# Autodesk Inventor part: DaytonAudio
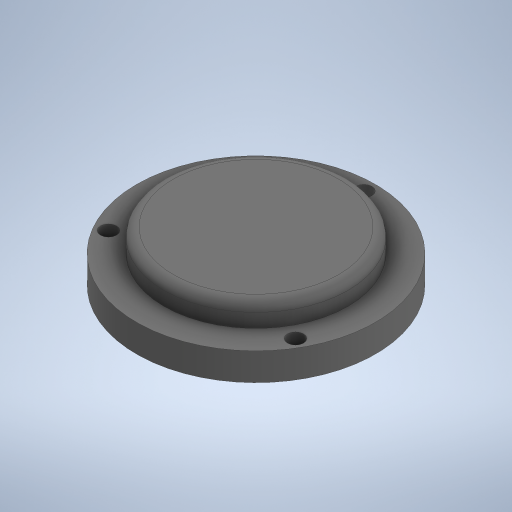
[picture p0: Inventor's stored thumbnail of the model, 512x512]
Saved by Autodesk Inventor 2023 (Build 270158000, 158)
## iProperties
Created: 2023-06
Part Number: DaytonAudio
Material: Generic
Document SubType Name: Modeling
Designer: Admin
Density: 1 g/cm^3
Appearance: Default
Author: Admin
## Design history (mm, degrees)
sketch "Sketch1"
  geometry: L1 (19.6, 6)-(0, 6); L2 (0, 6)-(-19.6, 6); C1 r 52 at (0, 0); C2 r 3.5 at (0, -47); C3 r 3.5 at (40.703, 23.5); C4 r 3.5 at (-40.703, 23.5); C5 r 2 at (19.6, 6); C6 r 2 at (0, -26.333); C7 r 2 at (-19.6, 6); A1 r 47 centre (0, 0) between (0, -47) and (-40.703, 23.5); 1 further point
  constraints: 8 centre point, 4 end point, 3 vertical alignment, 2 coincident, 2 collinear, 2 equal radius, 2 point on circle, 1 horizontal, 7 other
  dimensions: "d0" = 104 diameter of C1; "d1" = 94 diameter of A1; "d2" = 7 diameter of C2; "d5" = 360 deg dimension on A1.centre C2.centre (derived); "d9" = 19.6 horizontal distance of L1.start point (0, 0); "d10" = 6 vertical distance of point (0, 0) L1.start; "d11" = 4 diameter of C5; "d12" = 26.333 distance of C6.centre point (0, 0)
extrude "Extrusion1" new body sketch "Sketch1" distance "d7" = 12; taper "d8" = 0 deg
sketch "Sketch2"
  geometry: C1 r 40 at (0, 0); 1 further point
  constraints: 1 centre point, 1 coincident
  dimensions: "d14" = 80 diameter of C1
extrude "Extrusion2" join sketch "Sketch2" distance "d15" = 10; taper "d16" = 0 deg
fillet "Fillet1" dims "d17" = 4
body "Solid1"
